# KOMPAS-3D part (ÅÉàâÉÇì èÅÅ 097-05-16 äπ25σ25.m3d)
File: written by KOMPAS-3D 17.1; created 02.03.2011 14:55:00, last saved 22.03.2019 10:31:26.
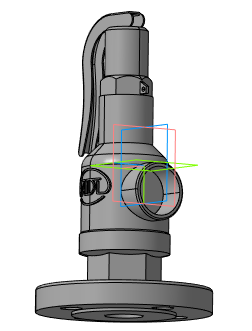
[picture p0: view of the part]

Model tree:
1. Плоскость XY
2. Плоскость ZX
3. Плоскость ZY
4. Ось X
5. Ось Y
6. Ось Z
7. Начало координат
8. Операция без истории:2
